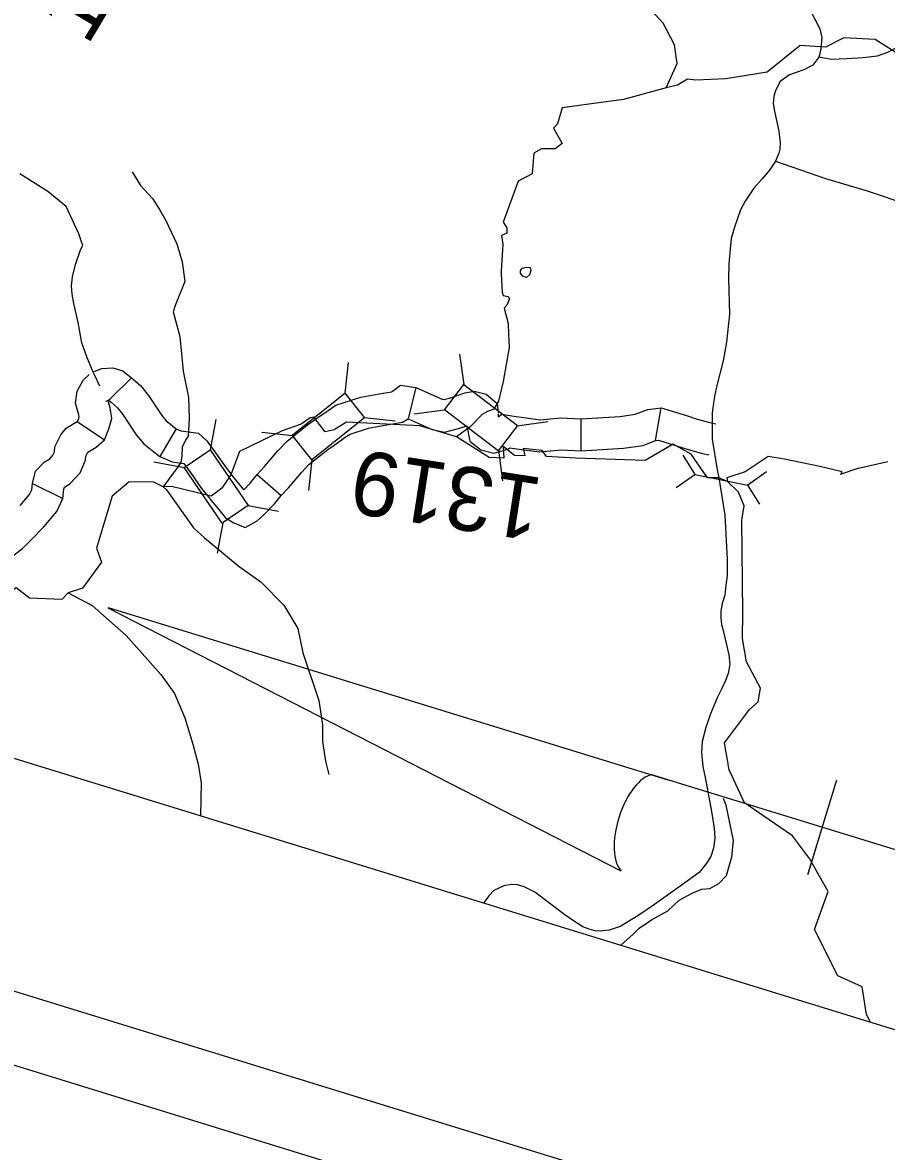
# Model space of a CAD drawing. Extents: x 1347947 to 1350662, y 1027710 to 1030532.
# Drawn here: x 1348130.6 to 1348191.6, y 1028722.6 to 1028802.3 of the extents above; entities that cross this region are included whole.
import ezdxf

# ---------------------------------------------------------------- set-up
doc = ezdxf.new("R2010")
doc.units = 0
for name, color, linetype in [('Default', 7, 'Continuous'), ('Prop Leader Line Light', 7, 'Continuous'), ('Prop North Arrow for Plan Sheets CELL', 7, 'Continuous'), ('Prop WCC CELL', 7, 'Continuous'), ('Sheet Title CELL', 7, 'Continuous')]:
    doc.layers.add(name, color=color, linetype=linetype)

msp = doc.modelspace()

# ---------------------------------------------------------------- linework, layer by layer
at = {"layer": 'Default'}
for p, q in [((1348161.441, 1028778.866), (1348161.73, 1028776.708)), ((1348153.569, 1028778.277), (1348153.331, 1028776.113)), ((1348138.275, 1028777.183), (1348136.803, 1028775.76)), ((1348158.356, 1028776.508), (1348157.807, 1028774.29)), ((1348158.22, 1028774.649), (1348160.378, 1028774.938)), ((1348175.28, 1028772.755), (1348175.677, 1028775.077)), ((1348134.43, 1028774.116), (1348136.354, 1028772.814)), ((1348144.218, 1028774.256), (1348143.819, 1028772.116)), ((1348156.889, 1028774.137), (1348154.725, 1028774.375)), ((1348165.514, 1028773.805), (1348167.672, 1028774.094)), ((1348169.995, 1028774.287), (1348169.999, 1028772.032)), ((1348141.43, 1028773.585), (1348140.262, 1028771.637)), ((1348149.636, 1028773.098), (1348147.472, 1028773.336)), ((1348150.999, 1028771.399), (1348150.761, 1028769.235)), ((1348164.192, 1028772.075), (1348164.481, 1028769.917)), ((1348177.201, 1028771.721), (1348178.053, 1028770.364)), ((1348139.841, 1028771.255), (1348141.981, 1028770.856)), ((1348147.133, 1028770.356), (1348148.841, 1028768.888)), ((1348176.745, 1028769.44), (1348178.053, 1028770.364)), ((1348178.053, 1028770.364), (1348181.796, 1028769.615)), ((1348183.104, 1028770.54), (1348181.796, 1028769.615)), ((1348131.274, 1028769.73), (1348133.409, 1028768.678)), ((1348182.647, 1028768.259), (1348181.796, 1028769.615)), ((1348146.507, 1028768.177), (1348148.647, 1028767.778)), ((1348144.711, 1028766.946), (1348144.312, 1028764.805))]:
    msp.add_line(p, q, dxfattribs=at)
for points in [[(1348177.63, 1028817.196), (1348177.951, 1028816.679), (1348178.604, 1028815.86), (1348179.239, 1028815.109), (1348179.785, 1028814.451), (1348180.251, 1028813.799), (1348180.826, 1028813.049), (1348181.502, 1028812.182), (1348181.961, 1028811.452), (1348182.308, 1028810.923), (1348182.713, 1028810.274), (1348183.069, 1028809.538), (1348183.436, 1028808.777), (1348183.946, 1028807.722), (1348184.527, 1028806.371), (1348185.137, 1028805.231), (1348185.814, 1028803.903), (1348186.876, 1028801.84), (1348187.025, 1028801.214), (1348186.961, 1028800.418), (1348186.847, 1028799.991), (1348186.821, 1028799.833)], [(1348176.029, 1028797.668), (1348176.808, 1028799.376), (1348176.614, 1028800.692), (1348175.809, 1028802.229), (1348175.269, 1028802.809), (1348174.914, 1028803.228), (1348174.138, 1028804.31), (1348173.439, 1028805.024), (1348172.827, 1028805.506), (1348172.457, 1028805.989), (1348171.235, 1028806.712), (1348170.086, 1028807.288), (1348167.778, 1028808.283), (1348165.346, 1028809.52), (1348163.641, 1028810.394), (1348162.603, 1028810.922)], [(1348200.195, 1028802.591), (1348199.82, 1028802.247), (1348199.539, 1028801.998), (1348199.118, 1028801.646), (1348198.794, 1028801.507), (1348198.476, 1028801.412), (1348198.072, 1028801.364), (1348197.346, 1028801.352), (1348196.79, 1028801.3), (1348196.159, 1028801.273), (1348195.752, 1028801.298), (1348195.36, 1028801.318), (1348194.841, 1028801.304), (1348194.427, 1028801.356), (1348194.204, 1028801.332), (1348193.468, 1028801.087), (1348192.72, 1028800.725), (1348191.656, 1028800.159), (1348190.927, 1028799.907), (1348189.94, 1028799.78), (1348188.78, 1028799.71), (1348187.697, 1028799.672), (1348186.821, 1028799.833)], [(1348192.653, 1028799.892), (1348190.781, 1028801.069), (1348188.577, 1028801.2), (1348187.285, 1028800.528), (1348185.5, 1028800.643), (1348183.157, 1028798.779), (1348180.234, 1028798.297), (1348178.116, 1028798.198), (1348177.531, 1028798.267), (1348176.819, 1028797.855), (1348176.029, 1028797.668), (1348173.009, 1028796.85), (1348170.918, 1028796.566), (1348168.694, 1028796.253), (1348168.349, 1028795.131), (1348168.065, 1028794.819), (1348168.682, 1028793.728), (1348168.197, 1028793.36), (1348167.223, 1028793.353), (1348166.678, 1028793.045), (1348166.572, 1028791.603), (1348165.572, 1028791.064), (1348164.509, 1028788.173), (1348164.786, 1028787.779), (1348164.782, 1028787.396), (1348164.388, 1028787.241), (1348164.49, 1028786.621), (1348164.378, 1028784.717)], [(1348186.821, 1028799.833), (1348186.378, 1028799.264), (1348185.747, 1028798.93), (1348185.212, 1028798.739), (1348184.744, 1028798.576), (1348184.076, 1028798.105), (1348183.756, 1028797.479), (1348183.634, 1028797.054), (1348183.592, 1028796.553), (1348183.67, 1028796.017), (1348183.757, 1028795.681), (1348183.993, 1028794.614), (1348184.089, 1028793.786), (1348184.057, 1028793.332), (1348183.982, 1028793.05), (1348183.751, 1028792.494)], [(1348183.751, 1028792.494), (1348183.323, 1028791.858), (1348182.804, 1028791.244), (1348182.21, 1028790.59), (1348181.598, 1028789.652), (1348181.288, 1028789.056), (1348180.852, 1028787.821), (1348180.614, 1028787.025), (1348180.544, 1028786.297), (1348180.464, 1028785.226), (1348180.433, 1028784.173), (1348180.504, 1028781.678), (1348180.293, 1028779.706), (1348180.048, 1028778.392), (1348179.606, 1028776.652), (1348179.439, 1028775.885), (1348179.288, 1028774.707), (1348179.283, 1028773.953), (1348179.282, 1028772.85)], [(1348183.751, 1028792.494), (1348187.272, 1028791.256), (1348190.213, 1028790.399), (1348193.156, 1028789.399), (1348193.699, 1028789.106), (1348194.712, 1028788.569), (1348195.143, 1028788.322), (1348195.92, 1028788.154), (1348198.65, 1028787.357), (1348200.732, 1028786.675), (1348202.535, 1028786.072), (1348203.816, 1028785.622), (1348205.314, 1028785.076), (1348207.576, 1028784.481), (1348208.014, 1028784.346), (1348208.259, 1028784.233), (1348208.846, 1028783.917), (1348209.48, 1028783.453), (1348210.049, 1028782.928)], [(1348136.043, 1028776.589), (1348135.674, 1028777.344), (1348135.56, 1028777.578), (1348135.228, 1028778.388), (1348135.141, 1028778.6), (1348134.754, 1028779.652), (1348134.504, 1028781.104), (1348134.193, 1028782.435), (1348134.081, 1028783.105), (1348134.032, 1028783.673), (1348134.096, 1028784.323), (1348134.318, 1028785.182), (1348134.675, 1028786.227), (1348134.835, 1028786.54), (1348134.711, 1028786.871), (1348134.537, 1028787.349), (1348133.648, 1028789.291), (1348132.364, 1028790.336), (1348130.388, 1028791.589)], [(1348138.312, 1028791.733), (1348138.911, 1028790.768), (1348139.748, 1028789.841), (1348140.252, 1028789.072), (1348140.696, 1028788.303), (1348141.479, 1028786.641), (1348141.855, 1028785.388), (1348142.038, 1028783.996), (1348141.342, 1028782.303), (1348141.218, 1028781.837), (1348141.69, 1028780.1), (1348141.912, 1028777.656), (1348142.283, 1028775.81), (1348142.35, 1028774.318), (1348142.274, 1028773.059), (1348142.076, 1028772.782), (1348141.842, 1028772.293), (1348141.832, 1028771.684), (1348141.759, 1028771.241), (1348141.49, 1028770.826), (1348140.509, 1028769.5)], [(1348165.895, 1028784.363), (1348165.729, 1028784.584), (1348165.743, 1028784.743), (1348165.85, 1028784.931), (1348166.144, 1028785.011), (1348166.417, 1028784.977), (1348166.468, 1028784.773), (1348166.378, 1028784.459), (1348166.168, 1028784.267), (1348165.895, 1028784.363)], [(1348164.378, 1028784.717), (1348164.365, 1028784.497), (1348164.435, 1028783.227), (1348164.521, 1028782.996), (1348164.863, 1028782.926), (1348164.974, 1028782.768), (1348164.77, 1028782.329), (1348164.595, 1028782.103), (1348164.861, 1028781.03), (1348164.892, 1028780.267)], [(1348164.892, 1028780.267), (1348164.93, 1028779.321), (1348164.508, 1028776.937), (1348164.18, 1028775.543), (1348163.852, 1028774.984), (1348163.402, 1028774.818), (1348163.04, 1028774.604), (1348162.175, 1028773.74), (1348161.222, 1028773.016)], [(1348135.633, 1028777.637), (1348136.178, 1028777.85), (1348136.952, 1028777.883), (1348137.645, 1028777.69), (1348138.275, 1028777.183), (1348138.892, 1028776.637), (1348139.47, 1028775.946), (1348140.408, 1028774.518), (1348140.716, 1028774.153), (1348141.133, 1028773.824), (1348141.43, 1028773.585), (1348141.741, 1028773.454), (1348143.005, 1028773.273), (1348143.587, 1028772.732), (1348144.323, 1028771.73), (1348145.015, 1028770.73), (1348145.522, 1028770.097)], [(1348130.411, 1028768.168), (1348131.07, 1028768.954), (1348131.218, 1028769.289), (1348131.274, 1028769.73), (1348131.486, 1028770.595), (1348132.096, 1028771.245), (1348132.493, 1028771.471), (1348132.715, 1028771.717), (1348132.824, 1028771.974), (1348132.865, 1028772.309), (1348133.284, 1028773.17), (1348133.643, 1028773.644), (1348134.43, 1028774.116), (1348134.473, 1028774.153), (1348134.545, 1028774.329), (1348134.579, 1028774.446), (1348134.559, 1028774.572), (1348134.31, 1028775.405), (1348134.424, 1028776.245), (1348134.863, 1028777.033), (1348135.282, 1028777.418)], [(1348151.293, 1028774.285), (1348152.151, 1028774.888), (1348152.708, 1028775.265), (1348154.467, 1028775.829), (1348155.769, 1028776.058), (1348156.623, 1028776.204), (1348156.708, 1028776.254), (1348157.265, 1028776.673), (1348158.356, 1028776.508), (1348160.199, 1028775.689), (1348160.328, 1028775.662), (1348160.716, 1028775.763), (1348161.811, 1028776.126), (1348162.466, 1028776.252), (1348163.316, 1028776.035), (1348164.097, 1028775.367), (1348164.16, 1028774.711)], [(1348129.876, 1028764.619), (1348130.581, 1028765.144), (1348131.144, 1028765.692), (1348132.083, 1028766.66), (1348132.998, 1028767.751), (1348133.409, 1028768.678), (1348133.49, 1028769.32), (1348133.527, 1028769.471), (1348133.923, 1028769.696), (1348134.637, 1028770.49), (1348135.019, 1028771.385), (1348135.053, 1028771.663), (1348135.192, 1028771.949), (1348135.766, 1028772.293), (1348136.354, 1028772.814), (1348136.674, 1028773.589), (1348136.879, 1028774.306), (1348136.758, 1028775.073), (1348136.614, 1028775.553), (1348136.652, 1028775.621), (1348136.803, 1028775.76)], [(1348136.452, 1028775.541), (1348136.636, 1028775.613), (1348136.823, 1028775.463), (1348137.275, 1028775.063), (1348137.661, 1028774.602), (1348138.602, 1028773.17), (1348139.144, 1028772.528), (1348139.73, 1028772.065), (1348140.262, 1028771.637), (1348141.132, 1028771.268), (1348141.957, 1028771.15), (1348142.491, 1028770.424), (1348143.209, 1028769.385), (1348143.766, 1028768.69)], [(1348151.625, 1028774.64), (1348151.625, 1028774.64)], [(1348164.164, 1028774.642), (1348164.171, 1028774.442), (1348164.422, 1028774.625), (1348165.267, 1028774.483), (1348166.133, 1028774.366), (1348167.14, 1028774.219), (1348168.597, 1028774.371), (1348169.995, 1028774.287), (1348172.78, 1028774.465), (1348173.839, 1028774.614), (1348174.725, 1028774.952), (1348175.677, 1028775.077), (1348177.454, 1028774.537), (1348178.223, 1028774.275), (1348179.118, 1028774.041), (1348179.531, 1028773.948)], [(1348151.939, 1028773.364), (1348151.152, 1028774.4), (1348150.875, 1028774.375), (1348150.244, 1028773.909), (1348148.903, 1028773.444), (1348145.887, 1028771.981), (1348145.286, 1028770.332), (1348144.644, 1028769.393)], [(1348145.511, 1028770.11), (1348146.137, 1028769.353), (1348146.198, 1028769.278), (1348146.676, 1028769.773), (1348147.133, 1028770.356), (1348147.668, 1028770.925), (1348148.613, 1028772.039), (1348149.282, 1028772.74), (1348150.798, 1028773.943), (1348151.299, 1028774.289)], [(1348161.222, 1028773.016), (1348158.641, 1028773.802), (1348153.457, 1028774.057), (1348152.59, 1028773.506), (1348151.939, 1028773.364)], [(1348152.586, 1028772.443), (1348153.43, 1028773.036), (1348153.703, 1028773.221), (1348155.008, 1028773.64), (1348156.153, 1028773.841), (1348157.407, 1028774.055), (1348157.807, 1028774.29), (1348159.502, 1028773.537), (1348160.382, 1028773.351), (1348161.354, 1028773.604), (1348161.939, 1028773.798)], [(1348161.939, 1028773.798), (1348162.153, 1028772.717), (1348162.95, 1028772.107), (1348163.852, 1028771.862), (1348164.851, 1028772.153), (1348164.986, 1028772.251), (1348165.82, 1028772.138), (1348167.094, 1028771.952), (1348168.647, 1028772.114), (1348169.999, 1028772.032), (1348173.01, 1028772.225), (1348174.404, 1028772.422), (1348175.28, 1028772.755), (1348175.489, 1028772.783), (1348176.763, 1028772.396), (1348177.574, 1028772.118), (1348178.585, 1028771.855), (1348179.033, 1028771.753)], [(1348176.534, 1028772.495), (1348174.534, 1028771.356), (1348169.625, 1028771.514), (1348167.572, 1028771.626), (1348167.264, 1028772.051), (1348165.934, 1028772.2), (1348166.047, 1028771.677), (1348165.327, 1028771.708), (1348164.518, 1028772.337), (1348164.573, 1028771.508), (1348163.536, 1028771.562), (1348161.222, 1028773.016)], [(1348143.777, 1028768.677), (1348144.401, 1028767.921), (1348144.915, 1028767.298), (1348145.486, 1028766.94), (1348146.297, 1028766.615), (1348147.138, 1028767.083), (1348147.637, 1028767.528), (1348148.375, 1028768.294), (1348148.841, 1028768.888), (1348149.346, 1028769.425), (1348150.287, 1028770.534), (1348150.802, 1028771.074), (1348152.139, 1028772.134), (1348152.579, 1028772.439)], [(1348179.282, 1028772.85), (1348179.641, 1028770.691), (1348179.736, 1028770.125), (1348180.179, 1028767.48), (1348180.282, 1028765.251), (1348180.336, 1028764.407), (1348180.339, 1028763.205), (1348180.243, 1028762.556), (1348180.161, 1028761.844), (1348179.988, 1028761.262), (1348179.899, 1028760.735), (1348179.889, 1028760.27), (1348179.922, 1028760.014), (1348179.926, 1028759.772), (1348180.035, 1028759.438), (1348180.46, 1028757.618), (1348180.52, 1028756.966), (1348180.409, 1028756.312), (1348180.224, 1028755.826), (1348179.961, 1028755.245), (1348179.634, 1028754.584), (1348179.148, 1028753.458), (1348178.833, 1028752.507), (1348178.579, 1028751.506), (1348178.53, 1028750.743), (1348178.617, 1028749.74), (1348178.789, 1028748.966), (1348179.236, 1028746.561), (1348179.424, 1028745.383), (1348179.476, 1028744.653), (1348179.378, 1028743.97), (1348179.19, 1028743.392), (1348178.827, 1028742.839), (1348178.367, 1028742.267), (1348177.516, 1028741.639), (1348175.207, 1028740.001), (1348174.03, 1028739.19), (1348172.778, 1028738.453), (1348172.004, 1028738.19), (1348171.563, 1028738.135), (1348171.096, 1028738.129), (1348170.584, 1028738.263), (1348170.154, 1028738.419), (1348169.487, 1028738.844), (1348168.881, 1028739.269), (1348166.746, 1028740.873), (1348166.005, 1028741.247), (1348165.54, 1028741.398), (1348165.108, 1028741.423), (1348164.567, 1028741.317), (1348163.863, 1028740.99), (1348163.502, 1028740.618), (1348163.126, 1028740.106)], [(1348179.736, 1028770.125), (1348179.736, 1028770.125), (1348178.942, 1028770.123), (1348177.8, 1028771.787), (1348176.534, 1028772.495)], [(1348191.689, 1028771.253), (1348189.497, 1028770.751), (1348188.323, 1028770.366), (1348188.451, 1028770.493), (1348188.366, 1028770.574), (1348186.878, 1028770.916), (1348184.378, 1028771.447), (1348183.22, 1028771.628), (1348181.606, 1028770.549), (1348180.32, 1028770.121), (1348180.351, 1028769.864)], [(1348144.644, 1028769.393), (1348143.903, 1028768.829), (1348141.092, 1028769.509), (1348140.509, 1028769.5), (1348139.853, 1028769.825), (1348138.102, 1028769.841), (1348136.904, 1028768.838), (1348135.786, 1028765.172), (1348136.154, 1028764.162), (1348134.816, 1028762.333), (1348133.797, 1028762.002), (1348133.354, 1028761.548), (1348131.073, 1028761.642), (1348130.128, 1028762.355), (1348129.182, 1028761.69), (1348128.137, 1028761.61), (1348128.137, 1028761.61)], [(1348180.351, 1028769.864), (1348179.736, 1028770.125)], [(1348181.525, 1028768.145), (1348181.143, 1028769.126), (1348180.351, 1028769.864)], [(1348140.509, 1028769.5), (1348140.74, 1028769.273), (1348142.657, 1028766.6), (1348143.43, 1028765.899), (1348145.881, 1028763.876), (1348147.398, 1028762.791), (1348149.021, 1028761.14), (1348150.01, 1028759.487), (1348150.366, 1028757.769), (1348151.492, 1028754.415), (1348151.762, 1028752.688), (1348151.755, 1028751.507), (1348151.964, 1028750.128), (1348152.197, 1028749.169)], [(1348181.382, 1028767.132), (1348181.525, 1028768.145)], [(1348190.469, 1028731.686), (1348190.173, 1028732.234), (1348189.879, 1028734.191), (1348188.144, 1028734.958), (1348186.51, 1028738.234), (1348187.465, 1028740.918), (1348186.158, 1028743.245), (1348184.941, 1028744.855), (1348182.848, 1028746.29), (1348181.552, 1028747.177), (1348180.488, 1028749.506), (1348180.147, 1028751.408), (1348181.905, 1028753.769), (1348182.53, 1028754.314), (1348182.695, 1028755.272), (1348181.706, 1028757.143), (1348181.426, 1028758.772), (1348181.449, 1028760.585), (1348181.382, 1028767.132)], [(1348133.797, 1028762.002), (1348135.482, 1028761.104), (1348137.9, 1028758.989), (1348140.339, 1028756.234), (1348141.297, 1028754.897), (1348142.024, 1028753.193), (1348142.609, 1028751.314), (1348142.969, 1028749.903), (1348143.185, 1028748.603), (1348143.133, 1028746.263)], [(1348172.824, 1028737.12), (1348173.697, 1028737.897), (1348174.119, 1028738.342), (1348174.992, 1028738.911), (1348176.135, 1028739.551), (1348176.95, 1028740.304), (1348177.909, 1028740.825), (1348178.553, 1028741.088), (1348179.101, 1028741.14), (1348179.752, 1028741.483), (1348180.279, 1028742.052), (1348180.677, 1028743.361), (1348180.781, 1028744.528), (1348180.268, 1028747.014), (1348180.087, 1028747.484)]]:
    msp.add_lwpolyline(points, dxfattribs=at)
for points in [[(1348161.73, 1028776.708), (1348165.52, 1028773.814), (1348164.168, 1028772.043), (1348160.378, 1028774.938)], [(1348154.725, 1028774.375), (1348151.005, 1028771.391), (1348149.611, 1028773.129), (1348153.331, 1028776.113)], [(1348143.819, 1028772.116), (1348146.515, 1028768.183), (1348144.678, 1028766.923), (1348141.981, 1028770.856)]]:
    msp.add_lwpolyline(points, close=True, dxfattribs=at)
at = {"layer": 'Prop North Arrow for Plan Sheets CELL'}
for p, q in [((1348136.625, 1028760.975), (1348136.613, 1028760.934)), ((1348136.625, 1028760.975), (1348136.613, 1028760.934)), ((1348172.841, 1028742.355), (1348136.613, 1028760.934)), ((1348136.625, 1028760.975), (1348176.14, 1028748.806)), ((1348196.641, 1028742.493), (1348174.983, 1028749.163)), ((1348176.14, 1028748.806), (1348175.024, 1028749.15)), ((1348186.046, 1028742.181), (1348188.083, 1028748.794)), ((1348186.937, 1028745.074), (1348186.034, 1028742.139)), ((1348186.034, 1028742.139), (1348186.021, 1028742.098))]:
    msp.add_line(p, q, dxfattribs=at)
msp.add_ellipse((1348174.304, 1028745.649), major_axis=(1.102, 3.489), ratio=0.461098, start_param=0.216388, end_param=2.908219, dxfattribs=at)
at = {"layer": 'Prop WCC CELL'}
msp.add_line((1348067.182, 1028769.652), (1348285.23, 1028702.505), dxfattribs=at)
at = {"layer": 'Sheet Title CELL'}
for p, q in [((1348848.447, 1028512.61), (1348050.431, 1028758.365)), ((1349023.782, 1028453.383), (1348048.96, 1028753.586))]:
    msp.add_line(p, q, dxfattribs=at)

# ---------------------------------------------------------------- texts
at = {"layer": 'Prop Leader Line Light'}
for s, rotation, p in [('1317', 59.19849, (1348135.143, 1028800.566)), ('1319', 171.14428, (1348167.45, 1028770.085))]:
    msp.add_text(s, height=4.5, rotation=rotation, dxfattribs=at).set_placement(p)

doc.saveas('drawing.dxf')
